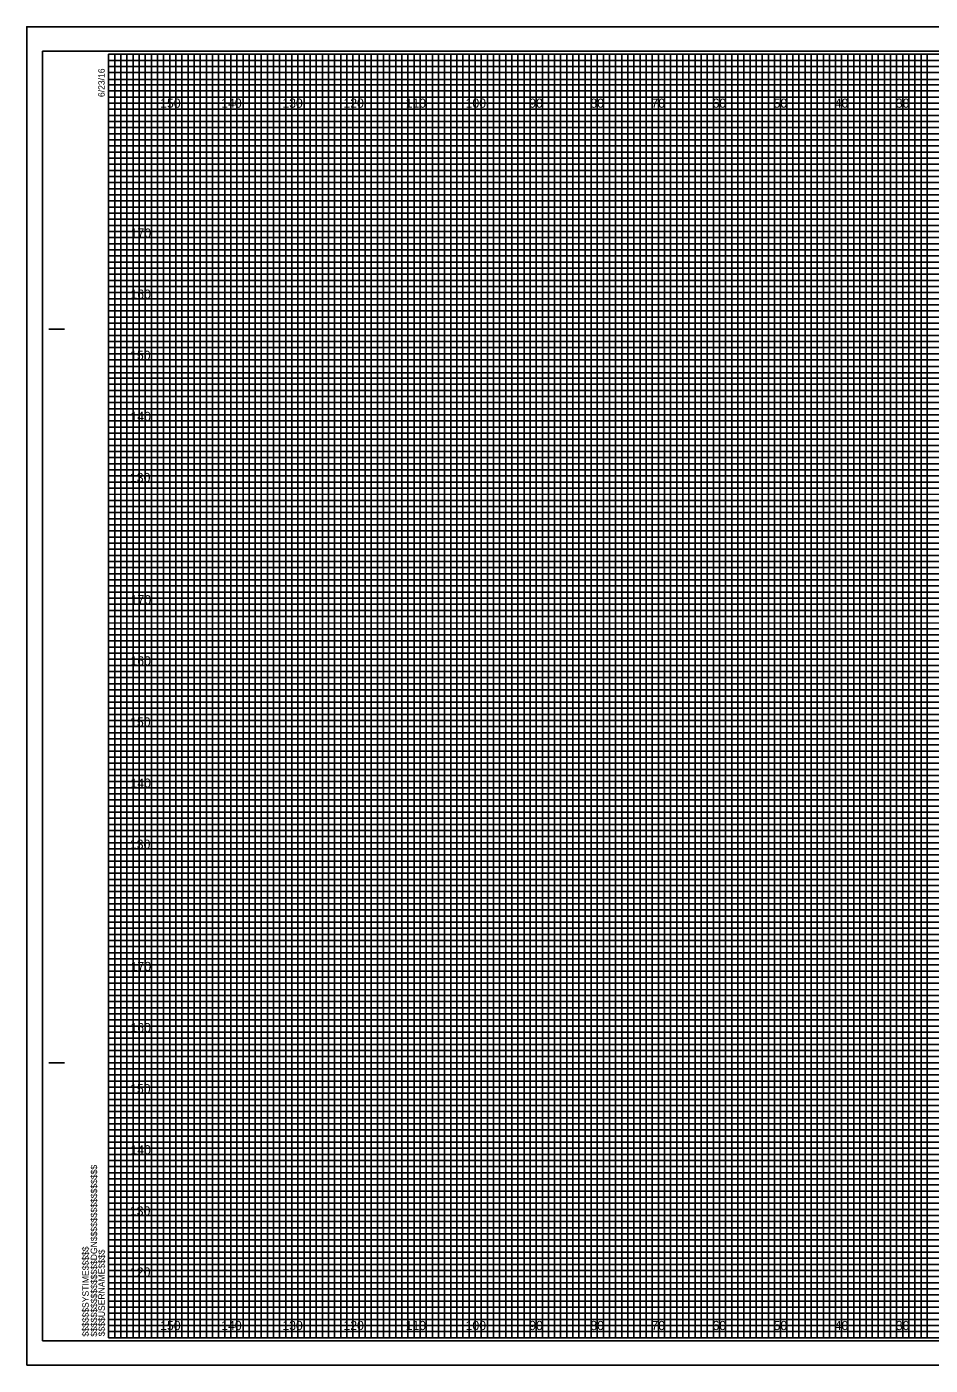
# Model space of a CAD drawing. Extents: x -13 to 323, y -5 to 1974.
# Drawn here: x -13.4 to 134.5, y 1755.5 to 1974.5 of the extents above; entities that cross this region are included whole.
import ezdxf

# ---------------------------------------------------------------- set-up
doc = ezdxf.new("R2010")
doc.units = 0
for name, color, linetype in [('Exist Cross Section Cell', 7, 'Continuous'), ('Exist XS Center Line Elevation Label', 7, 'Continuous'), ('Exist XS Ground Line', 7, 'Continuous'), ('Prop CMT Pvmt Course 1', 7, 'Continuous'), ('Prop CMT Pvmt Course 3', 7, 'Continuous'), ('Prop CMT Pvmt Surface', 7, 'Continuous'), ('Prop CMT Pvmt Surface Shoulder', 7, 'Continuous'), ('Prop CMT Shld Paved Course 1', 7, 'Continuous'), ('Prop CMT Shld Paved Course 2', 7, 'Continuous'), ('Prop CMT Shld Paved Course 3', 7, 'Continuous'), ('Prop CMT Subgrade Earthwork', 7, 'Continuous')]:
    doc.layers.add(name, color=color, linetype=linetype)

msp = doc.modelspace()

# ---------------------------------------------------------------- linework, layer by layer
at = {"layer": 'Exist XS Center Line Elevation Label'}
for points in [[(0, 1970), (5, 1970), (5, 1760), (15, 1760), (15, 1970), (25, 1970), (25, 1760), (35, 1760), (35, 1970), (45, 1970), (45, 1760), (55, 1760), (55, 1970), (65, 1970), (65, 1760), (75, 1760), (75, 1970), (85, 1970), (85, 1760), (95, 1760), (95, 1970), (105, 1970), (105, 1760), (115, 1760), (115, 1970), (125, 1970), (125, 1760), (135, 1760)], [(0, 1965), (275, 1965)], [(0, 1945), (320, 1945), (320, 1955), (0, 1955)], [(0, 1925), (320, 1925), (320, 1935), (0, 1935)], [(0, 1905), (320, 1905), (320, 1915), (0, 1915)], [(0, 1885), (320, 1885), (320, 1895), (0, 1895)], [(0, 1865), (320, 1865), (320, 1875), (0, 1875)], [(0, 1845), (320, 1845), (320, 1855), (0, 1855)], [(0, 1825), (320, 1825), (320, 1835), (0, 1835)], [(0, 1805), (320, 1805), (320, 1815), (0, 1815)], [(0, 1785), (320, 1785), (320, 1795), (0, 1795)], [(0, 1765), (320, 1765), (320, 1775), (0, 1775)]]:
    msp.add_lwpolyline(points, dxfattribs=at)
at = {"layer": 'Exist XS Ground Line'}
for p, q in [((10, 1970), (0, 1970)), ((10, 1760), (10, 1970)), ((30, 1970), (20, 1970)), ((20, 1970), (20, 1760)), ((30, 1760), (30, 1970)), ((50, 1970), (40, 1970)), ((40, 1970), (40, 1760)), ((50, 1760), (50, 1970)), ((70, 1970), (60, 1970)), ((60, 1970), (60, 1760)), ((70, 1760), (70, 1970)), ((90, 1970), (80, 1970)), ((80, 1970), (80, 1760)), ((90, 1760), (90, 1970)), ((110, 1970), (100, 1970)), ((100, 1970), (100, 1760)), ((110, 1760), (110, 1970)), ((130, 1970), (120, 1970)), ((120, 1970), (120, 1760)), ((130, 1760), (130, 1970)), ((20, 1760), (10, 1760)), ((40, 1760), (30, 1760)), ((60, 1760), (50, 1760)), ((80, 1760), (70, 1760)), ((100, 1760), (90, 1760)), ((120, 1760), (110, 1760)), ((140, 1760), (130, 1760))]:
    msp.add_line(p, q, dxfattribs=at)
for points in [[(0, 1960), (320, 1960), (320, 1950), (0, 1950)], [(0, 1940), (320, 1940), (320, 1930), (0, 1930)], [(0, 1920), (320, 1920), (320, 1910), (0, 1910)], [(0, 1900), (320, 1900), (320, 1890), (0, 1890)], [(0, 1880), (320, 1880), (320, 1870), (0, 1870)], [(0, 1860), (320, 1860), (320, 1850), (0, 1850)], [(0, 1840), (320, 1840), (320, 1830), (0, 1830)], [(0, 1820), (320, 1820), (320, 1810), (0, 1810)], [(0, 1800), (320, 1800), (320, 1790), (0, 1790)], [(0, 1780), (320, 1780), (320, 1770), (0, 1770)]]:
    msp.add_lwpolyline(points, dxfattribs=at)
at = {"layer": 'Prop CMT Pvmt Course 3'}
msp.add_lwpolyline([(-13.4, 1755.5), (323.3, 1755.5), (323.3, 1974.5), (-13.4, 1974.5)], close=True, dxfattribs=at)
at = {"layer": 'Prop CMT Pvmt Surface'}
for p, q in [((10, 1760), (10, 1970)), ((20, 1760), (20, 1970)), ((30, 1760), (30, 1970)), ((40, 1760), (40, 1970)), ((50, 1760), (50, 1970)), ((60, 1760), (60, 1970)), ((70, 1760), (70, 1970)), ((80, 1760), (80, 1970)), ((90, 1760), (90, 1970)), ((100, 1760), (100, 1970)), ((110, 1760), (110, 1970)), ((120, 1760), (120, 1970)), ((130, 1760), (130, 1970)), ((0, 1960), (320, 1960)), ((0, 1950), (320, 1950)), ((0, 1940), (320, 1940)), ((0, 1930), (320, 1930)), ((0, 1920), (320, 1920)), ((0, 1910), (320, 1910)), ((0, 1900), (320, 1900)), ((0, 1890), (320, 1890)), ((0, 1880), (320, 1880)), ((0, 1870), (320, 1870)), ((0, 1860), (320, 1860)), ((0, 1850), (320, 1850)), ((0, 1840), (320, 1840)), ((0, 1830), (320, 1830)), ((0, 1820), (320, 1820)), ((0, 1810), (320, 1810)), ((0, 1800), (320, 1800)), ((0, 1790), (320, 1790)), ((0, 1780), (320, 1780)), ((0, 1770), (320, 1770))]:
    msp.add_line(p, q, dxfattribs=at)
at = {"layer": 'Prop CMT Pvmt Surface Shoulder'}
for p, q in [((323.3, 1974.5), (-13.4, 1974.5)), ((-13.4, 1974.5), (-13.4, 1755.5)), ((-13.4, 1755.5), (323.3, 1755.5))]:
    msp.add_line(p, q, dxfattribs=at)
at = {"layer": 'Prop CMT Shld Paved Course 1'}
for p, q in [((0, 1969), (260, 1969)), ((260, 1967.98), (0, 1967.98)), ((0, 1967.98), (0, 1967)), ((0, 1967), (260, 1967)), ((260, 1965.89), (0, 1965.89)), ((0, 1965.89), (0, 1964)), ((0, 1964), (320, 1964))]:
    msp.add_line(p, q, dxfattribs=at)
for points in [[(0, 1963), (270, 1963), (320, 1963), (320, 1962), (0, 1962)], [(0, 1961), (320, 1961), (320, 1959), (0, 1959)], [(0, 1958), (320, 1958), (320, 1957), (0, 1956.98)], [(0, 1956), (320, 1956), (320, 1954), (0, 1954)], [(0, 1953), (320, 1953), (320, 1952), (0, 1952)], [(0, 1951), (320, 1951), (320, 1949), (0, 1949)], [(0, 1948), (320, 1948), (320, 1947), (0, 1947)], [(0, 1946), (320, 1946), (320, 1944), (0, 1944)], [(0, 1943), (320, 1943), (320, 1942), (0, 1942)], [(0, 1941), (320, 1941), (320, 1939), (0, 1939)], [(0, 1938), (320, 1938), (320, 1937), (0, 1937)], [(0, 1936), (320, 1936), (320, 1933.95), (320, 1933), (320, 1932), (0, 1932)], [(0, 1934), (320, 1934), (320, 1933), (0, 1933)], [(0, 1931), (320, 1931), (320, 1929), (0, 1929.03)], [(0, 1929.03), (320, 1929), (320, 1928), (0, 1928)], [(0, 1927), (320, 1927), (320, 1926), (0, 1926)], [(0, 1924), (320, 1924), (320, 1923), (0, 1923)], [(0, 1922), (320, 1922), (320, 1921), (0, 1921)], [(-0.07, 1918.89), (320, 1918.89), (320, 1917.88), (-0.07, 1917.88)], [(0, 1917), (320, 1917), (320, 1916), (0, 1916)], [(0, 1914), (320, 1914), (320, 1913), (0, 1913)], [(0, 1912), (320, 1912), (320, 1911), (0, 1911)], [(0, 1909), (320, 1909), (320, 1908), (0, 1908)], [(0, 1907), (320, 1907), (320, 1906), (0, 1906)], [(0, 1904), (320, 1904), (320, 1903), (0, 1903)], [(0, 1902), (320, 1902), (320, 1901), (0, 1901)], [(0, 1899), (320, 1899), (319.99, 1897.98), (0, 1898)], [(0, 1897), (320, 1897), (320, 1896), (0, 1896)], [(0, 1894), (320, 1894), (320, 1893), (0, 1893)], [(0, 1892), (320, 1892), (320, 1891), (0, 1891)], [(0, 1889), (320, 1889), (320, 1888), (0, 1888)], [(0, 1887), (320, 1887), (320, 1886), (0, 1886)], [(0, 1884), (320, 1884), (320, 1883), (0, 1883)], [(0, 1882), (320, 1882), (320, 1881), (0, 1881)], [(0, 1879), (320, 1879), (320, 1878), (0, 1878)], [(0, 1876.99), (320.07, 1876.91), (320, 1876), (0, 1876)], [(0, 1874), (320, 1874), (320, 1873), (0, 1873)], [(0, 1872), (320, 1872), (320, 1871), (0, 1871)], [(0, 1869), (320, 1869), (320, 1868), (0, 1868)], [(0, 1867), (320, 1867), (320, 1866), (0, 1866)], [(0, 1864), (320, 1864), (320, 1863), (0, 1863)], [(0, 1862), (320, 1862), (320, 1861), (0, 1861)], [(0, 1859), (320, 1859), (320, 1858), (0, 1858)], [(0, 1857), (320, 1857), (320, 1856), (0, 1856)], [(0, 1854), (320, 1854), (320, 1853), (0, 1853)], [(0, 1852), (320, 1852), (320, 1851), (0, 1851)], [(0, 1849), (320, 1849), (320, 1848), (0, 1848)], [(0, 1847), (320, 1847), (320, 1846), (0, 1846)], [(0, 1844), (320, 1844), (320, 1843), (0, 1843)], [(0, 1842), (320, 1842), (320, 1841), (0, 1841)], [(0, 1839), (320, 1839), (319.99, 1837.98), (0, 1838)], [(0, 1837), (320, 1837), (320, 1836), (0, 1836)], [(0, 1834), (320, 1834), (320, 1833), (0, 1833)], [(0, 1832), (320, 1832), (320, 1831), (0, 1831)], [(0, 1829), (320, 1829), (320, 1828), (0, 1828)], [(0, 1827), (320, 1827), (320, 1826), (0, 1826)], [(0, 1824), (320, 1824), (320, 1823), (0, 1823)], [(0, 1822), (320, 1822), (320, 1821), (0, 1821)], [(0, 1819), (320, 1819), (320, 1818), (0, 1818)], [(0, 1816.99), (320.07, 1816.91), (320, 1816), (0, 1816)], [(0, 1814), (320, 1814), (320, 1813), (0, 1813)], [(0, 1812), (320, 1812), (320, 1811), (0, 1811)], [(0, 1809), (320, 1809), (320, 1808), (0, 1808)], [(0, 1807), (320, 1807), (320, 1806), (0, 1806)], [(0, 1804), (320, 1804), (320, 1803), (0, 1803)], [(0, 1802), (320, 1802), (320, 1801), (0, 1801)], [(0, 1799), (320, 1799), (320, 1798), (0, 1798)], [(0, 1797), (320, 1797), (320, 1796), (0, 1796)], [(0, 1794), (320, 1794), (320, 1793), (0, 1793)], [(0, 1792), (320, 1792), (320, 1791), (0, 1791)], [(0, 1789), (320, 1789), (320, 1788), (0, 1788)], [(0, 1787), (320, 1787), (320, 1786), (0, 1786)], [(0, 1784), (320, 1784), (320, 1783), (0, 1783)], [(0, 1782), (320, 1782), (320, 1781), (0, 1781)], [(0, 1779), (320, 1779), (320, 1778), (0, 1778)], [(0, 1777), (320, 1777), (320, 1776), (0, 1776)], [(0, 1774), (320, 1774), (320, 1773), (0, 1773)], [(0, 1772), (320, 1772), (320, 1771), (0, 1771)], [(0, 1769), (320, 1769), (320, 1768), (0, 1768)], [(0, 1767), (320, 1767), (320, 1766), (0, 1766)], [(0, 1764), (320, 1764), (320, 1763), (0, 1763)], [(0, 1762), (320, 1762), (320, 1761), (0, 1761)]]:
    msp.add_lwpolyline(points, dxfattribs=at)
at = {"layer": 'Prop CMT Shld Paved Course 2'}
for p, q in [((-9.8, 1925), (-7.3, 1925)), ((-9.7, 1925), (-7.2, 1925)), ((-9.8, 1805), (-7.3, 1805)), ((-9.7, 1805), (-7.2, 1805)), ((0, 1760), (0, 1760)), ((0, 1760), (0, 1760)), ((0, 1760), (0, 1760)), ((0, 1760), (0, 1760)), ((0, 1760), (0, 1760)), ((0, 1760), (0, 1760)), ((0, 1760), (0, 1760))]:
    msp.add_line(p, q, dxfattribs=at)
msp.add_lwpolyline([(320, 1970), (0, 1970), (0, 1760), (320, 1760)], close=True, dxfattribs=at)
at = {"layer": 'Prop CMT Shld Paved Course 3'}
for points in [[(0, 1760), (1, 1760), (1, 1970), (2, 1970), (2, 1760)], [(2, 1760), (3, 1760), (3, 1970), (4, 1970), (4, 1760)], [(5, 1760), (6, 1760), (6, 1970), (7, 1970), (7, 1760)], [(7, 1760), (8, 1760), (8, 1970), (9, 1970), (9, 1760)], [(10, 1760), (11, 1760), (11, 1970), (12, 1970), (12, 1760)], [(12, 1760), (13, 1760), (13, 1970), (14, 1970), (14, 1760)], [(15, 1760), (16, 1760), (16, 1970), (17, 1970), (17, 1760)], [(17, 1760), (18, 1760), (18, 1970), (19, 1970), (19, 1760)], [(20, 1760), (21, 1760), (21, 1970), (22, 1970), (22, 1760)], [(22, 1760), (23, 1760), (23, 1970), (24, 1970), (24, 1760)], [(25, 1760), (26, 1760), (26, 1970), (27, 1970), (27, 1760)], [(27, 1760), (28, 1760), (28, 1970), (29, 1970), (29, 1760)], [(30, 1760), (31, 1760), (31, 1970), (32, 1970), (32, 1760)], [(32, 1760), (33, 1760), (33, 1970), (34, 1970), (34, 1760)], [(35, 1760), (36, 1760), (36, 1970), (37, 1970), (37, 1760)], [(37, 1760), (38, 1760), (38, 1970), (39, 1970), (39, 1760)], [(40, 1760), (41, 1760), (41, 1970), (42, 1970), (42, 1760)], [(42, 1760), (43, 1760), (43, 1970), (44, 1970), (44, 1760)], [(45, 1760), (46, 1760), (46, 1970), (47, 1970), (47, 1760)], [(47, 1760), (48, 1760), (48, 1970), (49, 1970), (49, 1760)], [(50, 1760), (51, 1760), (51, 1970), (52, 1970), (52, 1760)], [(52, 1760), (53, 1760), (53, 1970), (54, 1970), (54, 1760)], [(55, 1760), (56, 1760), (56, 1970), (57, 1970), (57, 1760)], [(57, 1760), (58, 1760), (58, 1970), (59, 1970), (59, 1760)], [(60, 1760), (61, 1760), (61, 1970), (62, 1970), (62, 1760)], [(62, 1760), (63, 1760), (63, 1970), (64, 1970), (64, 1760)], [(65, 1760), (66, 1760), (66, 1970), (67, 1970), (67, 1760)], [(67, 1760), (68, 1760), (68, 1970), (69, 1970), (69, 1760)], [(70, 1760), (71, 1760), (71, 1970), (72, 1970), (72, 1760)], [(72, 1760), (73, 1760), (73, 1970), (74, 1970), (74, 1760)], [(75, 1760), (76, 1760), (76, 1970), (77, 1970), (77, 1760)], [(77, 1760), (78, 1760), (78, 1970), (79, 1970), (79, 1760)], [(80, 1760), (81, 1760), (81, 1970), (82, 1970), (82, 1760)], [(82, 1760), (83, 1760), (83, 1970), (84, 1970), (84, 1760)], [(85, 1760), (86, 1760), (86, 1970), (87, 1970), (87, 1760)], [(87, 1760), (88, 1760), (88, 1970), (89, 1970), (89, 1760)], [(90, 1760), (91, 1760), (91, 1970), (92, 1970), (92, 1760)], [(92, 1760), (93, 1760), (93, 1970), (94, 1970), (94, 1760)], [(95, 1760), (96, 1760), (96, 1970), (97, 1970), (97, 1760)], [(97, 1760), (98, 1760), (98, 1970), (99, 1970), (99, 1760)], [(100, 1760), (101, 1760), (101, 1970), (102, 1970), (102, 1760)], [(102, 1760), (103, 1760), (103, 1970), (104, 1970), (104, 1760)], [(105, 1760), (106, 1760), (106, 1970), (107, 1970), (107, 1760)], [(107, 1760), (108, 1760), (108, 1970), (109, 1970), (109, 1760)], [(110, 1760), (111, 1760), (111, 1970), (112, 1970), (112, 1760)], [(112, 1760), (113, 1760), (113, 1970), (114, 1970), (114, 1760)], [(115, 1760), (116, 1760), (116, 1970), (117, 1970), (117, 1760)], [(117, 1760), (118, 1760), (118, 1970), (119, 1970), (119, 1760)], [(120, 1760), (121, 1760), (121, 1970), (122, 1970), (122, 1760)], [(122, 1760), (123, 1760), (123, 1970), (124, 1970), (124, 1760)], [(125, 1760), (126, 1760), (126, 1970), (127, 1970), (127, 1760)], [(127, 1760), (128, 1760), (128, 1970), (129, 1970), (129, 1760)], [(130, 1760), (131, 1760), (131, 1970), (132, 1970), (132, 1760)], [(132, 1760), (133, 1760), (133, 1970), (134, 1970), (134, 1760)]]:
    msp.add_lwpolyline(points, dxfattribs=at)
at = {"layer": 'Prop CMT Subgrade Earthwork'}
msp.add_lwpolyline([(-10.8, 1759.5), (322.4, 1759.5), (322.4, 1970.5), (-10.8, 1970.5)], close=True, dxfattribs=at)

# ---------------------------------------------------------------- texts
at = {"layer": 'Exist Cross Section Cell'}
for s, p in [('150', (8.44, 1961.25)), ('140', (18.44, 1961.25)), ('130', (28.44, 1961.25)), ('120', (38.44, 1961.25)), ('110', (48.62, 1961.25)), ('100', (58.44, 1961.25)), ('90', (68.86, 1961.25)), ('80', (78.86, 1961.25)), ('70', (88.86, 1961.25)), ('60', (98.86, 1961.25)), ('50', (108.86, 1961.25)), ('40', (118.86, 1961.25)), ('30', (128.86, 1961.25)), ('150', (8.44, 1761.25)), ('140', (18.44, 1761.25)), ('130', (28.44, 1761.25)), ('120', (38.44, 1761.25)), ('110', (48.62, 1761.25)), ('100', (58.44, 1761.25)), ('90', (68.86, 1761.25)), ('80', (78.86, 1761.25)), ('70', (88.86, 1761.25)), ('60', (98.86, 1761.25)), ('50', (108.86, 1761.25)), ('40', (118.86, 1761.25)), ('30', (128.86, 1761.25))]:
    msp.add_text(s, height=1.5, dxfattribs=at).set_placement(p)
at = {"layer": 'Prop CMT Pvmt Course 1'}
for s, p in [('170', (3.61, 1940)), ('160', (3.57, 1930)), ('150', (3.52, 1920)), ('140', (3.57, 1910)), ('130', (3.49, 1900)), ('170', (3.61, 1880)), ('160', (3.57, 1870)), ('150', (3.52, 1860)), ('140', (3.57, 1850)), ('130', (3.49, 1840)), ('170', (3.61, 1820)), ('160', (3.57, 1810)), ('150', (3.52, 1800)), ('140', (3.57, 1790)), ('130', (3.49, 1780)), ('120', (3.5, 1770))]:
    msp.add_text(s, height=1.5, dxfattribs=at).set_placement(p)
at = {"layer": 'Prop CMT Shld Paved Course 2'}
for s, p in [('6/23/16', (-0.65, 1963)), ('$$$$$$$$$$$$$$$$DGN$$$$$$$$$$$$$$$$', (-1.88, 1760.18)), ('$$$$$$SYSTIME$$$$$', (-3.26, 1760.18)), ('$$$$USERNAME$$$$', (-0.62, 1760.23))]:
    msp.add_text(s, height=1.05, rotation=90, dxfattribs=at).set_placement(p)

doc.saveas('drawing.dxf')
